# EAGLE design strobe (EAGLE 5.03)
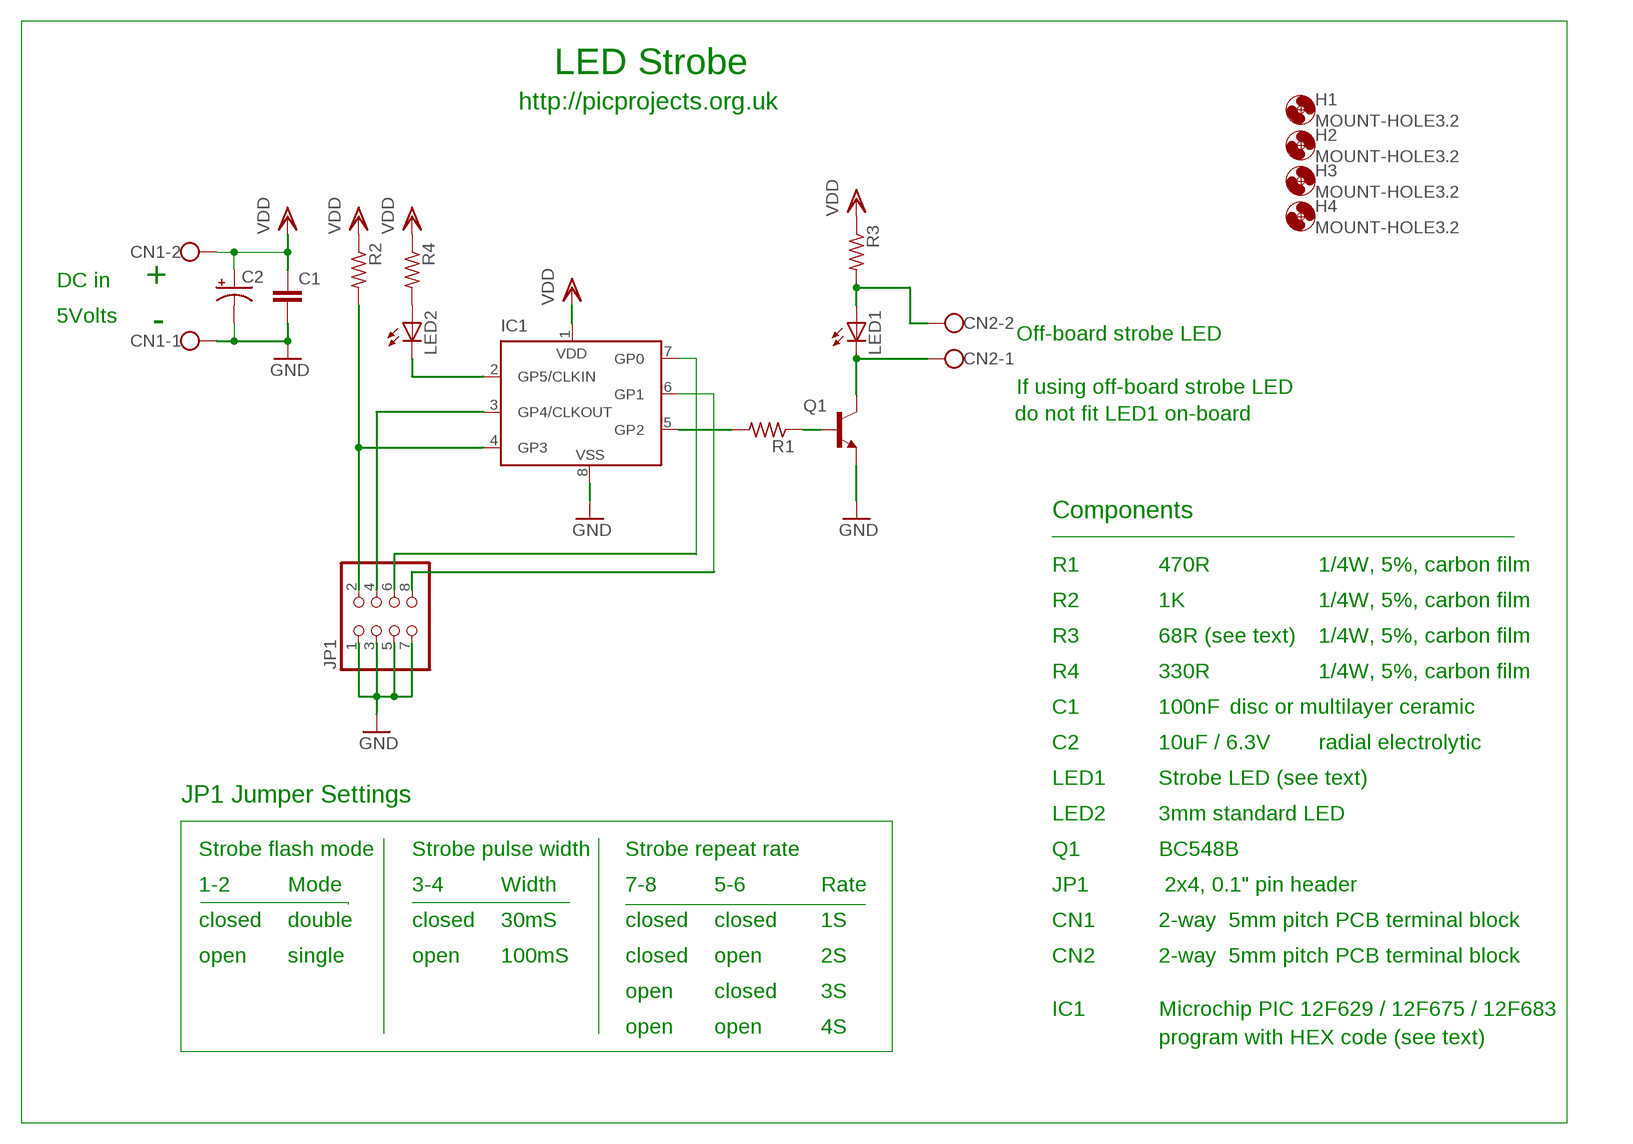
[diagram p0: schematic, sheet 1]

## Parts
C1  C-EU025-024X044  [C025-024X044]
C2  CPOL-USE2-5  [E2-5]
CN1  W237-102  [W237-102]
CN2  W237-102  [W237-102]
H1  MOUNT-HOLE3.2  [3,2]
H2  MOUNT-HOLE3.2  [3,2]
H3  MOUNT-HOLE3.2  [3,2]
H4  MOUNT-HOLE3.2  [3,2]
IC1  PIC12F629P  [DIL8]
JP1  PINHD-2X4  [2X04]
LED1  LED5MM  [LED5MM]
LED2  LED3MM  [LED3MM]
Q1  BC547  [TO92]
R1  R-US_0207/10  [0207/10]
R2  R-US_0207/10  [0207/10]
R3  R-US_0207/10  [0207/10]
R4  R-US_0207/10  [0207/10]

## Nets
GND: C1.2 C2.- CN1.1 IC1.8(VSS) JP1.1 JP1.3 JP1.5 JP1.7 Q1.1(E)
N$1: IC1.5(GP2) R1.2
N$2: IC1.3(GP4/CLKOUT) JP1.4
N$3: IC1.4(GP3) JP1.2 R2.2
N$4: IC1.6(GP1) JP1.8
N$5: IC1.7(GP0) JP1.6
N$6: Q1.2(B) R1.1
N$7: CN2.1 LED1.K(C) Q1.3(C)
N$8: LED2.A R4.2
N$9: CN2.2 LED1.A R3.2
N$10: IC1.2(GP5/CLKIN) LED2.K(C)
VDD: C1.1 C2.+ CN1.2 IC1.1(VDD) R2.1 R3.1 R4.1

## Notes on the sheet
- LED Strobe
- http://picprojects.org.uk
- DC in | +
- 5Volts
- -
- Off-board strobe LED
- If using off-board strobe LED
- do not fit LED1 on-board
- Components
- R1 | 470R | 1/4W, 5%, carbon film
- R2 | 1K | 1/4W, 5%, carbon film
- R3 | 68R (see text) | 1/4W, 5%, carbon film
- R4 | 330R | 1/4W, 5%, carbon film
- C1 | 100nF | disc or multilayer ceramic
- C2 | 10uF / 6.3V | radial electrolytic
- LED1 | Strobe LED (see text)
- JP1 Jumper Settings
- LED2 | 3mm standard LED
- Strobe flash mode | Strobe pulse width | Strobe repeat rate | Q1 | BC548B
- 1-2 | Mode | 3-4 | Width | 7-8 | 5-6 | Rate | JP1 | 2x4, 0.1" pin header
- closed | double | closed | 30mS | closed | closed | 1S | CN1 | 2-way  5mm pitch PCB terminal block
- open | single | open | 100mS | closed | open | 2S | CN2 | 2-way  5mm pitch PCB terminal block
- open | closed | 3S
- IC1 | Microchip PIC 12F629 / 12F675 / 12F683
- open | open | 4S
- program with HEX code (see text)

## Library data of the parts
C1 = rcl:C-EU: CAPACITOR, European symbol
C2 = rcl:CPOL-US: POLARIZED CAPACITOR, American symbol
CN1 CN2 = con-wago-500:W237-102: WAGO SCREW CLAMP
H1-H4 = holes:MOUNT-HOLE: MOUNTING HOLE with drill center marker
IC1 = microchip:PIC12F6*: Data Sheet 8-Pin FLASH-Based 8-Bit CMOS Microcontrollers Source: http://www.microchip.com .. 41190c.pdf
JP1 = pinhead:PINHD-2X4: PIN HEADER
LED1 LED2 = led:LED: LED
Q1 = transistor:BC547: NPN TRANSISTOR
R1-R4 = rcl:R-US_: RESISTOR, American symbol

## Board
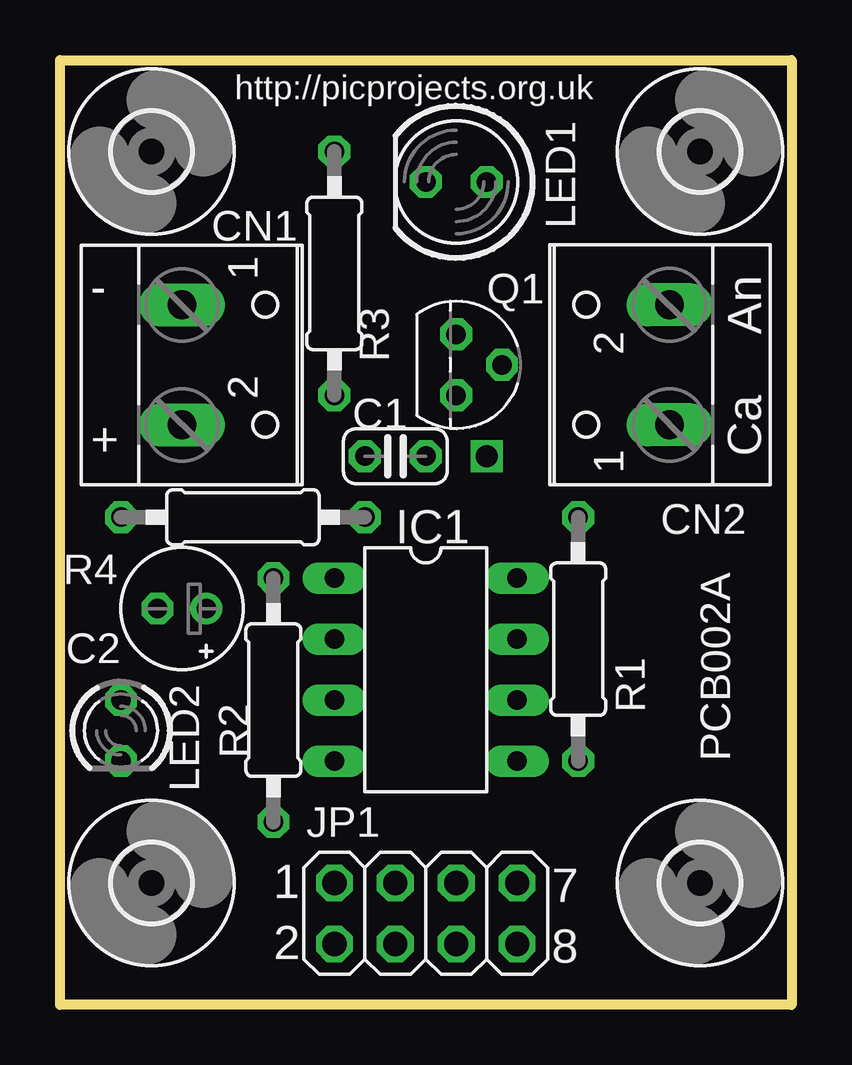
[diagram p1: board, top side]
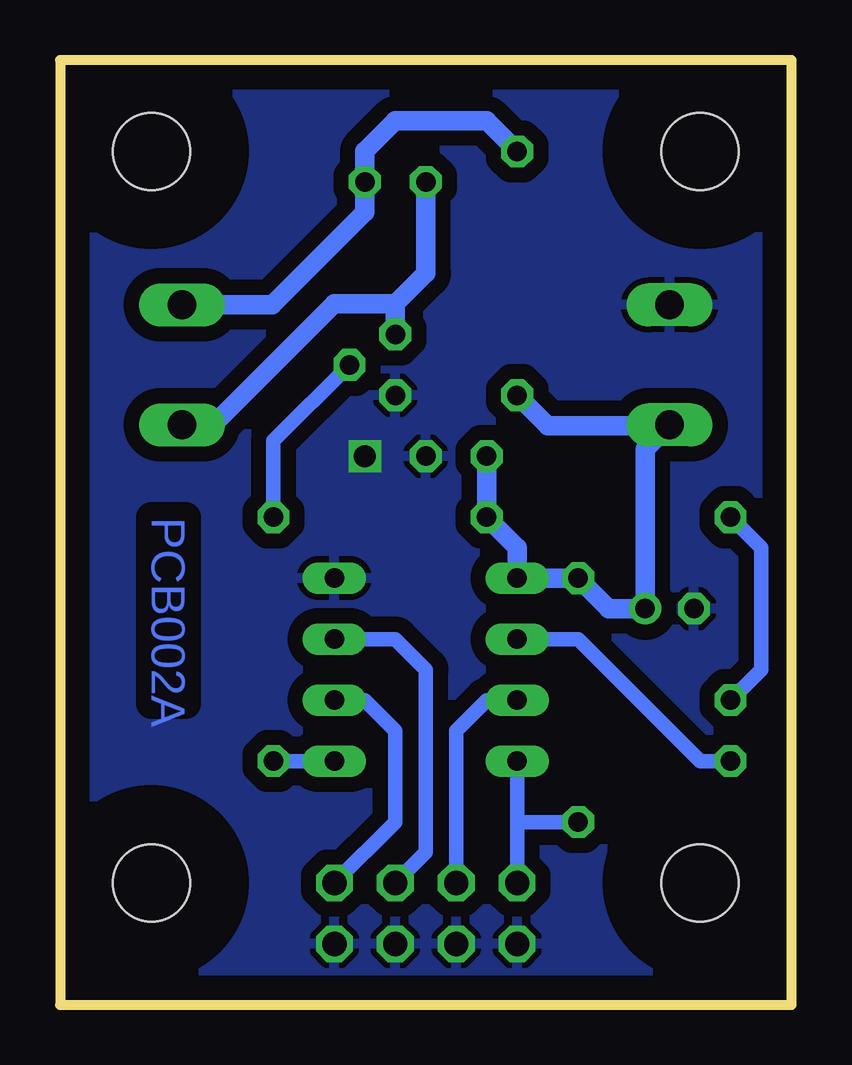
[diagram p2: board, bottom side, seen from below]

Size 30.48 x 39.37 mm. Coordinates in mm from the lower left corner, seen from the top.
Outline: 0,39.37 30.48,39.37 30.48,0 0,0 0,39.37
Copper layers (1*16): Top 0.035mm / dielectric 1.5mm / Bottom 0.035mm
Design rules "default *": minimum track width 10mil, minimum drill 24mil, track to track 25mil, track to pad 25mil, pad to pad 8mil, via to via 8mil, smd to smd 8mil, copper to edge 40mil, drill to drill 8mil, minimum pad ring 10mil, minimum via ring 8mil, stop-mask expansion 4mil, vias tented up to drill 0mil, thermal gap 10mil

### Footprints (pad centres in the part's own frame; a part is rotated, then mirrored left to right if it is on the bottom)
C025-024X044 = drill 0.813 octagon: 1 -1.27,0; 2 1.27,0
E2-5 = drill 0.813 pad 1.27 round: + -1.016,0 | drill 0.813 pad 1.27 octagon: - 1.016,0
W237-102 = drill 1.194 long: 1 -2.5,-1.27; 2 2.5,-1.27
3,2 = hole 3.2: 0,0
DIL8 = drill 0.813 long: 1 -3.81,-3.81; 2 -1.27,-3.81; 3 1.27,-3.81; 4 3.81,-3.81; 5 3.81,3.81; 6 1.27,3.81; 7 -1.27,3.81; 8 -3.81,3.81
2X04 = drill 1.016 octagon: 1 -3.81,-1.27; 2 -3.81,1.27; 3 -1.27,-1.27; 4 -1.27,1.27; 5 1.27,-1.27; 6 1.27,1.27; 7 3.81,-1.27; 8 3.81,1.27
LED5MM = drill 0.813 octagon: A -1.27,0; K 1.27,0
LED3MM = drill 0.813 octagon: A -1.27,0; K 1.27,0
TO92 = drill 0.813 octagon: 1 1.27,0; 2 0,1.905; 3 -1.27,0
0207/10 = drill 0.813 octagon: 1 -5.08,0; 2 5.08,0

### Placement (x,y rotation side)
C1  13.97,22.86 0 top
C2  5.08,16.51 180 top
CN1  6.35,26.67 270 top
CN2  24.13,26.67 90 top
H1  3.81,5.08 0 top
H2  26.67,5.08 0 top
H3  3.81,35.56 0 top
H4  26.67,35.56 0 top
IC1  15.24,13.97 270 top
JP1  15.24,3.81 0 top
LED1  16.51,34.29 180 top
LED2  2.54,11.43 270 top
Q1  16.51,26.67 270 top
R1  21.59,15.24 270 top
R2  8.89,12.7 270 top
R3  11.43,30.48 90 top
R4  7.62,20.32 180 top

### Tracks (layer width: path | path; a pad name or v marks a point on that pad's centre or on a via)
GND  (via drill 0.9)
  other vias: 17.78,22.86
  pour Bottom: 0,39.37 30.48,39.37 30.48,0 0,0
N$1
  Bottom 0.61: IC1.5 R1.2
N$2
  Bottom 0.61: JP1.4 13.97,11.43 12.7,12.7 IC1.3
N$3
  Bottom 0.61: JP1.2 11.43,7.62 | 11.43,7.62 IC1.4 | 11.43,7.62 R2.2
N$4
  Bottom 0.61: JP1.8 16.51,7.62 16.51,11.43 17.78,12.7 IC1.6
N$5
  Bottom 0.61: JP1.6 15.24,6.35 15.24,13.97 16.51,15.24 IC1.7
N$6
  Bottom 0.61: R1.1 21.59,23.5 Q1.2
N$7
  Bottom 0.813: CN2.1 24.17,24.17 24.13,24.13 19.05,29.21 16.51,29.21 | 16.51,29.21 15.24,30.48 LED1.K | Q1.3 16.51,29.21
N$8
  Bottom 0.61: LED2.A 1.27,13.97 1.27,19.05 R4.2
N$9
  Bottom 0.813: CN2.2 21.63,29.17 17.78,33.02 LED1.A 17.78,35.56 16.51,36.83 12.7,36.83 R3.2
N$10
  Bottom 0.61: LED2.K 3.81,10.16 8.89,15.24 IC1.2
VDD
  Bottom 0.254: CN1.2 6.35,24.13
  Bottom 0.813: CN1.2 6.1,23.15 C2.+ 7.62,16.51 R2.1 IC1.1 11.43,19.05 R4.1 C1.1 | R3.1 10.16,24.13 6.35,24.13 5.08,24.13

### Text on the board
Bottom: PCB002A
tNames: http://picprojects.org.uk | - | An | + | Ca | PCB002A | 7 | 1 | 8 | 2
Document: DC in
